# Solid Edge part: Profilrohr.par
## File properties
Username: bmolnar
Dokumentum tartalom típus: 0
Author: bmolnar
Last saved by: bmolnar
Revision: 87
Sűrűség: 0,000 kg/m^3
Pontosság: 0,990
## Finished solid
Body 1: solid body, 95 faces, 278 edges, 184 vertices.
  Faces by surface: plane 48, cylinder 47
  Edges by curve: line 184, circle 94
Bounding box of the edges (mm): 65.500 x 65.500 x 96.000, from (-32.75, -32.75, 0) to (32.75, 32.75, 96).
Cylindrical faces by radius (mm): R0.15 x20, R0.25 x20, R6.5 x2, R8 x4, R25 x1
Planar faces by outward normal: +x 11, +y 12, +z 1, -x 11, -y 12, -z 1
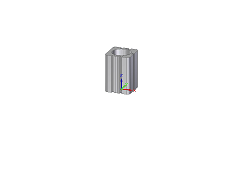
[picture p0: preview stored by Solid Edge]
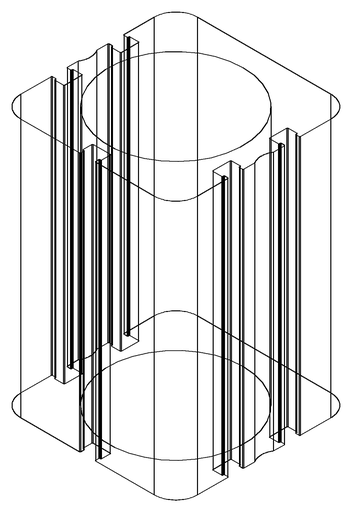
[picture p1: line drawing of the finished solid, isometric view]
